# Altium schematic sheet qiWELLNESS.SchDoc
size A3; DocumentNumber: 1; SheetNumber: 1; SheetTotal: 2
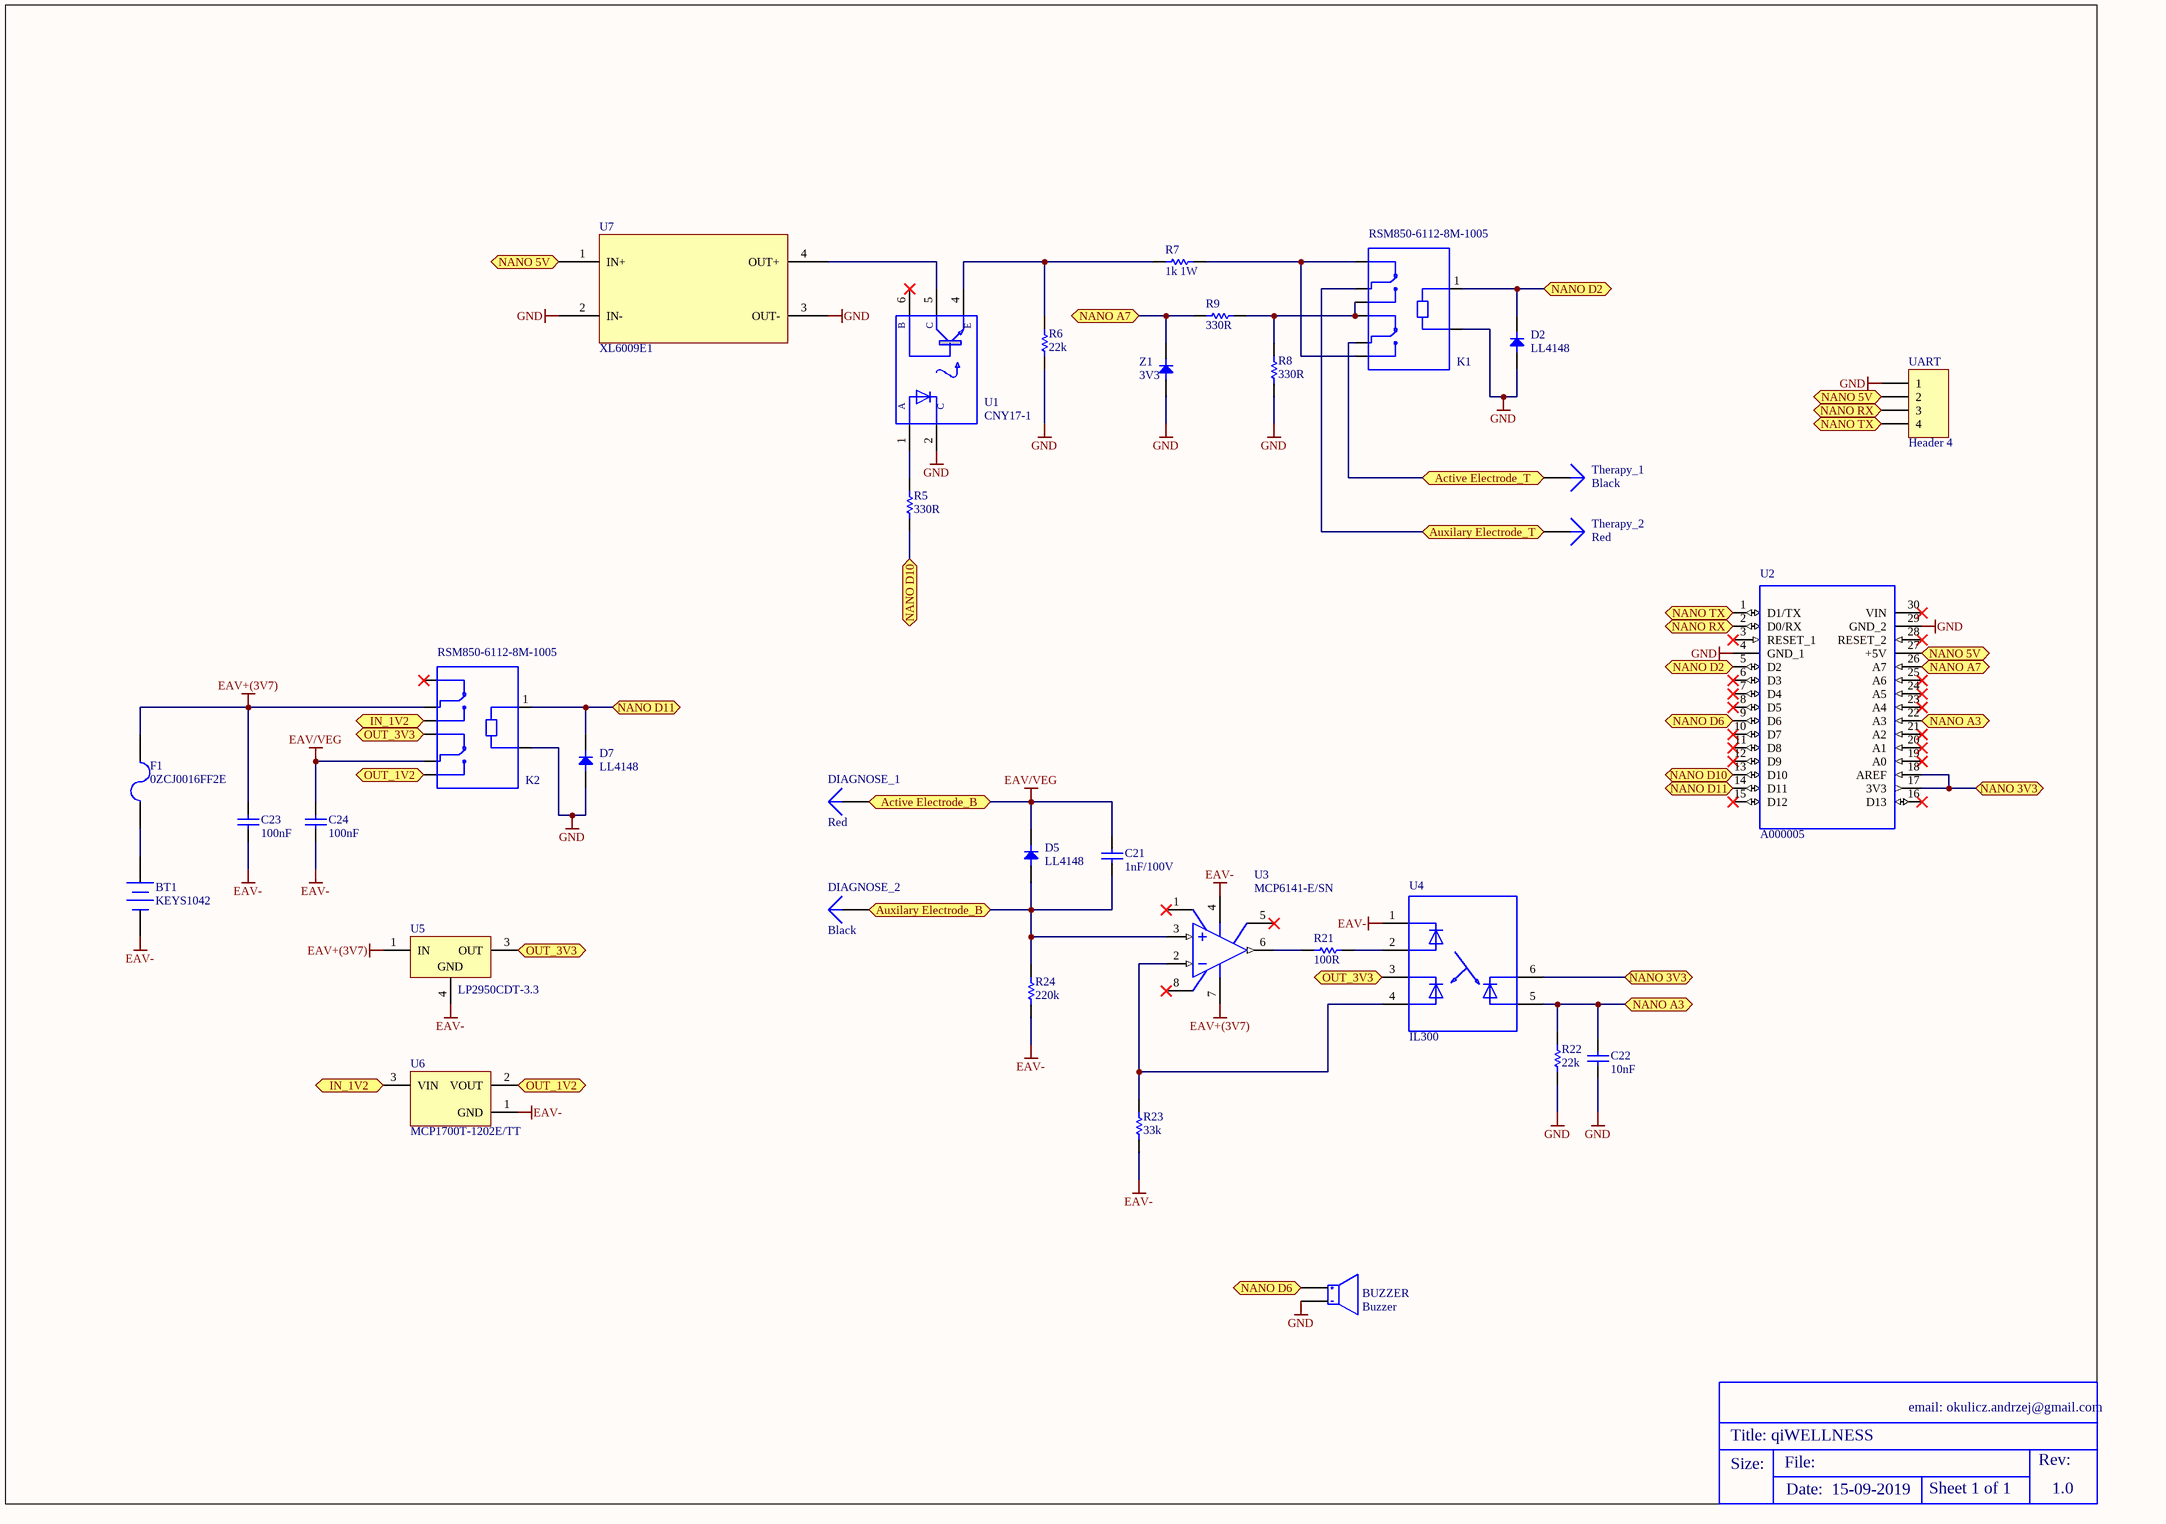
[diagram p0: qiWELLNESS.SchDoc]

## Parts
BT1  KEYS1042  [KEYS1042]
BUZZER  Buzzer  [BUZZER]
C21  1nF/100V  [0805]
C22  10nF  [0805]
C23  100nF  [0805]
C24  100nF  [0805]
D2  LL4148  [SOD-80]
D5  LL4148  [SOD-80]
D7  LL4148  [SOD-80]
DIAGNOSE_1  Red  [PAD]
DIAGNOSE_2  Black  [PAD]
F1  0ZCJ0016FF2E  [3216[1206]]
K1  RSM850-6112-8M-1005  [RELAY_RSM850-6112-8M-1005]
K2  RSM850-6112-8M-1005  [RELAY_RSM850-6112-8M-1005]
R5  330R  [0805]
R6  22k  [0805]
R7  1k 1W  [1T-2512]
R8  330R  [0805]
R9  330R  [0805]
R21  100R  [0805]
R22  22k  [0805]
R23  33k  [0805]
R24  220k  [0805]
Therapy_1  Black  [PAD]
Therapy_2  Red  [PAD]
U1  CNY17-1  [OPTOCOUPLER_H11F3SR2M]
U2  A000005  [ARDUINO_A000005]
U3  MCP6141-E/SN  [DIP_SOP_8]
U4  IL300  [DIP8]
U5  LP2950CDT-3.3  [369A-13]
U6  MCP1700T-1202E/TT  [SOT-23-TT3_L]
U7  XL6009E1  [XL6009E1]
UART  Header 4  [HDR1X4]
Z1  3V3  [SOD-80]

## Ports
Active Electrode_B (bidir), Active Electrode_T (bidir), Auxilary Electrode_B (bidir), Auxilary Electrode_T (bidir), IN_1V2 (bidir), NANO 3V3 (bidir), NANO 5V (bidir), NANO A3 (bidir), NANO A7 (bidir), NANO D2 (bidir), NANO D6 (bidir), NANO D10 (bidir), NANO D11 (bidir), NANO RX (bidir), NANO TX (bidir), OUT_1V2 (bidir), OUT_3V3 (bidir)

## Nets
EAV+(3V7): C23.2 F1.2 K2.3 U3.7(VDD) U5.1(IN)
EAV-: BT1.2(-) C23.1 C24.1 R23.1 R24.1 U3.4(VSS) U4.1(C1) U5.4(GND) U6.1(GND)
EAV/VEG: C21.2 C24.2 D5.2(K) DIAGNOSE_1.1 K2.8 ; port Active Electrode_B
GND: BUZZER.2 C22.1 D2.1(A) D7.1(A) K1.10 K2.10 R6.2 R8.2 R22.1 U1.2(C) U2.4(GND_1) U2.29(GND_2) U7.2(IN-) U7.3(OUT-) UART.1 Z1.1(A)
Active Electrode_T: K1.8 Therapy_1.1 ; port Active Electrode_T
Auxilary Electrode_B: C21.1 D5.1(A) DIAGNOSE_2.1 R24.2 U3.3(VIN+) ; port Auxilary Electrode_B
Auxilary Electrode_T: K1.3 Therapy_2.1 ; port Auxilary Electrode_T
IN_1V2: K2.4 U6.3(VIN) ; port IN_1V2
NANO 3V3: U2.17(3V3) U2.18(AREF) U4.6(C3) ; port NANO 3V3
NANO 5V: U2.27(+5V) U7.1(IN+) UART.2 ; port NANO 5V
NANO A3: C22.2 R22.2 U2.22(A3) U4.5(A3) ; port NANO A3
NANO A7: R9.1 U2.26(A7) Z1.2(K) ; port NANO A7
NANO D2: D2.2(K) K1.1 U2.5(D2) ; port NANO D2
NANO D6: BUZZER.1 U2.9(D6) ; port NANO D6
NANO D10: R5.2 U2.13(D10) ; port NANO D10
NANO D11: D7.2(K) K2.1 U2.14(D11) ; port NANO D11
NANO RX: U2.2(D0/RX) UART.3 ; port NANO RX
NANO TX: U2.1(D1/TX) UART.4 ; port NANO TX
OUT_1V2: K2.7 U6.2(VOUT) ; port OUT_1V2
OUT_3V3: K2.9 U4.3(C2) U5.3(OUT) ; port OUT_3V3
NetBT1_1: BT1.1(+) F1.1
NetK1_2: K1.2 K1.7 R7.2
NetK1_4: K1.4 K1.9 R8.1 R9.2
NetR5_1: R5.1 U1.1(A)
NetR6_1: R6.1 R7.1 U1.4(E)
NetR21_1: R21.1 U3.6(VOUT)
NetR21_2: R21.2 U4.2(A1)
NetR23_2: R23.2 U3.2(VIN-) U4.4(A2)
NetU1_5: U1.5(C`) U7.4(OUT+)

Not connected (* = marked no-connect by the designer): K2 2*; U1 6(B)*; U2 3(RESET_1)* 6(D3)* 7(D4)* 8(D5)* 10(D7)* 11(D8)* 12(D9)* 15(D12)* 16(D13)* 19(A0)* 20(A1)* 21(A2)* 23(A4)* 24(A5)* 25(A6)* 28(RESET_2)* 30(VIN)*; U3 1(NC)* 5(NC)* 8(NC)*

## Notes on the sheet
- Title: qiWELLNESS
- email: okulicz.andrzej@gmail.com
- Size:
- File:
- Date:  15-09-2019
- Sheet 1 of 1
- Rev:
- 1.0

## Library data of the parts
BT1 = Battery: 18650 Battery 3.6-3.7V LiOn 2200-3400mAh
BUZZER = SPEAKER: Buzzer 5V; Manufacturer: LOUDITY; Manufacturer PN: LD-BZEG-1205
C21-C24 = Cap: Capacitor
D2 D5 D7 Z1 = DIODE: Switching Diode
DIAGNOSE_1 DIAGNOSE_2 Therapy_1 Therapy_2 = Plug
F1 = Fuse 2: Fuse
K1 K2 = 1-1462033-4
R5 = Res1: Chip Resistor 5% 0.1W; Manufacturer: Generic
R6 R8 R9 R21-R24 = Res1: Chip Resistor 5% 0.1W
R7 = ERJ1T: Thick Film Chip Resistor, 1 Ohm to 1M Ohm Range, 5% Tolerance, 2512 Size, 1 W
U1 = CNY17-1: CNY17 Series Single Channel 70 V 5000 Vrms Phototransistor Optocoupler - DIP-6
U2 = A000005: MICRO, ARDUINO NANO 3.0, MINI-B USB, ATmega328, 0.1DIP, ICSP HDR
U3 = MCP6141-E/SN: 600 nA, Non-Unity Gain Rail-to-Rail Input/Output Operational Amplifier, 8-Pin SOIC, Extended Temperature
U4 = IL300: IL300 Series Single Channel 5300 Vrms Wide Bandwidth Linear Optocoupler - DIP-8; MF: Vishay
U5 = LP2950CDT-3.3: MicroPower Voltage Regulator; Note: Pin 2 is electrically connected to Pin 4 (TAB); Pin 2 is trimmed and not drawn
U6 = MCP1700T-1202E/TT: Low Quiescent Current LDO, 3-Pin SOT-23, Extended Temperature, Tape and Reel
U7 = XL6009E1: Step-Up OUT 5V-40V
UART = Header 4: Header, 4-Pin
